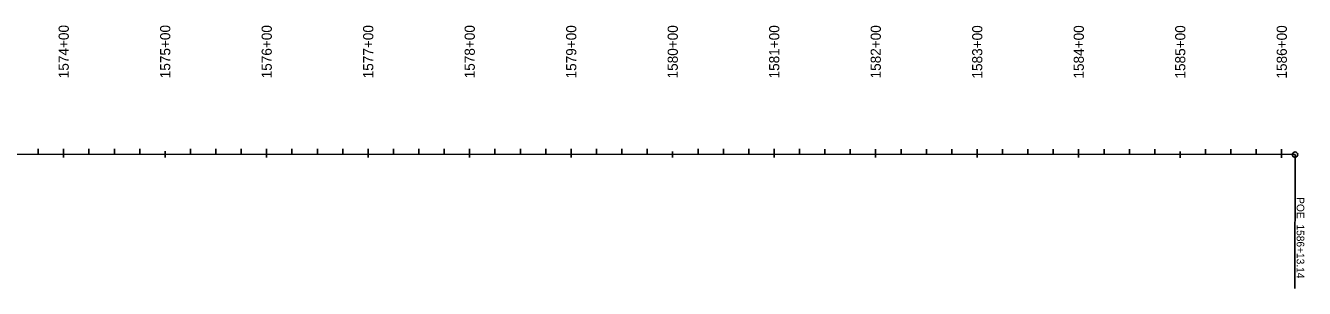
# Model space of a CAD drawing. Extents: x 21596470 to 21601942, y 8263806 to 8275912.
# Drawn here: x 21600682 to 21601942, y 8275652 to 8275911 of the extents above; entities that cross this region are included whole.
import ezdxf

# ---------------------------------------------------------------- set-up
doc = ezdxf.new("R2010")
doc.units = 0
for name, color, linetype in [('DsnShtInsideBorder', 7, 'Continuous'), ('Level 1', 7, 'Continuous'), ('Level 20', 7, 'Continuous'), ('wetNoteSoil', 7, 'Continuous')]:
    doc.layers.add(name, color=color, linetype=linetype)

msp = doc.modelspace()

# ---------------------------------------------------------------- linework, layer by layer
at = {"layer": 'DsnShtInsideBorder'}
for p in [(21601932.5, 8275784.2), (21601932.4, 8275652.2)]:
    msp.add_line(p, (21601932.4, 8275652.2), dxfattribs=at)
msp.add_circle((21601932.5, 8275784.2), 2.67, dxfattribs=at)
at = {"layer": 'Level 1'}
for p, q in [((21600719.3, 8275784.5), (21600719.3, 8275789.9)), ((21600819.3, 8275787.5), (21600819.3, 8275781.4)), ((21600919.3, 8275784.4), (21600919.3, 8275789.9)), ((21601019.3, 8275784.4), (21601019.3, 8275789.9)), ((21601119.3, 8275784.4), (21601119.3, 8275789.8)), ((21601219.3, 8275784.4), (21601219.3, 8275789.8)), ((21601319.3, 8275787.4), (21601319.3, 8275781.3)), ((21601419.3, 8275784.3), (21601419.3, 8275789.8)), ((21601519.3, 8275784.3), (21601519.3, 8275789.7)), ((21601619.3, 8275784.2), (21601619.3, 8275789.7)), ((21601719.3, 8275784.2), (21601719.3, 8275789.7)), ((21601819.3, 8275787.3), (21601819.3, 8275781.1)), ((21601919.3, 8275784.2), (21601919.3, 8275789.6))]:
    msp.add_line(p, q, dxfattribs=at)
at = {"layer": 'Level 20'}
for p in [(21598714.2, 8275785), (21599270.9, 8275784.9)]:
    msp.add_line(p, (21601932.5, 8275784.2), dxfattribs=at)
at = {"layer": 'wetNoteSoil'}
for p, q in [((21600694.3, 8275784.5), (21600694.3, 8275789.9)), ((21600719.3, 8275787.5), (21600719.3, 8275781.4)), ((21600744.3, 8275784.5), (21600744.3, 8275789.9)), ((21600769.3, 8275784.5), (21600769.3, 8275789.9)), ((21600794.3, 8275784.5), (21600794.3, 8275789.9)), ((21600819.3, 8275787.5), (21600819.3, 8275781.4)), ((21600844.3, 8275784.4), (21600844.3, 8275789.9)), ((21600869.3, 8275784.4), (21600869.3, 8275789.9)), ((21600894.3, 8275784.4), (21600894.3, 8275789.9)), ((21600919.3, 8275787.5), (21600919.3, 8275781.4)), ((21600944.3, 8275784.4), (21600944.3, 8275789.9)), ((21600969.3, 8275784.4), (21600969.3, 8275789.9)), ((21600994.3, 8275784.4), (21600994.3, 8275789.9)), ((21601019.3, 8275787.5), (21601019.3, 8275781.3)), ((21601044.3, 8275784.4), (21601044.3, 8275789.9)), ((21601069.3, 8275784.4), (21601069.3, 8275789.8)), ((21601094.3, 8275784.4), (21601094.3, 8275789.8)), ((21601119.3, 8275787.4), (21601119.3, 8275781.3)), ((21601144.3, 8275784.4), (21601144.3, 8275789.8)), ((21601169.3, 8275784.4), (21601169.3, 8275789.8)), ((21601194.3, 8275784.4), (21601194.3, 8275789.8)), ((21601219.3, 8275787.4), (21601219.3, 8275781.3)), ((21601244.3, 8275784.3), (21601244.3, 8275789.8)), ((21601269.3, 8275784.3), (21601269.3, 8275789.8)), ((21601294.3, 8275784.3), (21601294.3, 8275789.8)), ((21601319.3, 8275787.4), (21601319.3, 8275781.3)), ((21601344.3, 8275784.3), (21601344.3, 8275789.8)), ((21601369.3, 8275784.3), (21601369.3, 8275789.8)), ((21601394.3, 8275784.3), (21601394.3, 8275789.8)), ((21601419.3, 8275787.4), (21601419.3, 8275781.2)), ((21601444.3, 8275784.3), (21601444.3, 8275789.8)), ((21601469.3, 8275784.3), (21601469.3, 8275789.7)), ((21601494.3, 8275784.3), (21601494.3, 8275789.7)), ((21601519.3, 8275787.3), (21601519.3, 8275781.2)), ((21601544.3, 8275784.3), (21601544.3, 8275789.7)), ((21601569.3, 8275784.3), (21601569.3, 8275789.7)), ((21601594.3, 8275784.3), (21601594.3, 8275789.7)), ((21601619.3, 8275787.3), (21601619.3, 8275781.2)), ((21601644.3, 8275784.2), (21601644.3, 8275789.7)), ((21601669.3, 8275784.2), (21601669.3, 8275789.7)), ((21601694.3, 8275784.2), (21601694.3, 8275789.7)), ((21601719.3, 8275787.3), (21601719.3, 8275781.2)), ((21601744.3, 8275784.2), (21601744.3, 8275789.7)), ((21601769.3, 8275784.2), (21601769.3, 8275789.7)), ((21601794.3, 8275784.2), (21601794.3, 8275789.7)), ((21601819.3, 8275787.3), (21601819.3, 8275781.1)), ((21601844.3, 8275784.2), (21601844.3, 8275789.7)), ((21601869.3, 8275784.2), (21601869.3, 8275789.6)), ((21601894.3, 8275784.2), (21601894.3, 8275789.6)), ((21601919.3, 8275787.2), (21601919.3, 8275781.1))]:
    msp.add_line(p, q, dxfattribs=at)

# ---------------------------------------------------------------- texts
at = {"layer": 'DsnShtInsideBorder'}
for s, p in [('POE ', (21601934.1, 8275742.2)), ('1586+13.14', (21601934.1, 8275715.3))]:
    msp.add_text(s, height=7.5, rotation=269.9853, dxfattribs=at).set_placement(p)
at = {"layer": 'Level 1'}
for s, p in [('1575+00', (21600824.4, 8275859.5)), ('1580+00', (21601324.4, 8275859.3)), ('1585+00', (21601824.4, 8275859.2))]:
    msp.add_text(s, height=10.02, rotation=89.9853, dxfattribs=at).set_placement(p)
at = {"layer": 'wetNoteSoil'}
for s, p in [('1574+00', (21600724.4, 8275859.5)), ('1575+00', (21600824.4, 8275859.5)), ('1576+00', (21600924.4, 8275859.4)), ('1577+00', (21601024.4, 8275859.4)), ('1578+00', (21601124.4, 8275859.4)), ('1579+00', (21601224.4, 8275859.3)), ('1580+00', (21601324.4, 8275859.3)), ('1581+00', (21601424.4, 8275859.3)), ('1582+00', (21601524.4, 8275859.3)), ('1583+00', (21601624.4, 8275859.2)), ('1584+00', (21601724.4, 8275859.2)), ('1585+00', (21601824.4, 8275859.2)), ('1586+00', (21601924.4, 8275859.2))]:
    msp.add_text(s, height=10.02, rotation=89.9853, dxfattribs=at).set_placement(p)

doc.saveas('drawing.dxf')
